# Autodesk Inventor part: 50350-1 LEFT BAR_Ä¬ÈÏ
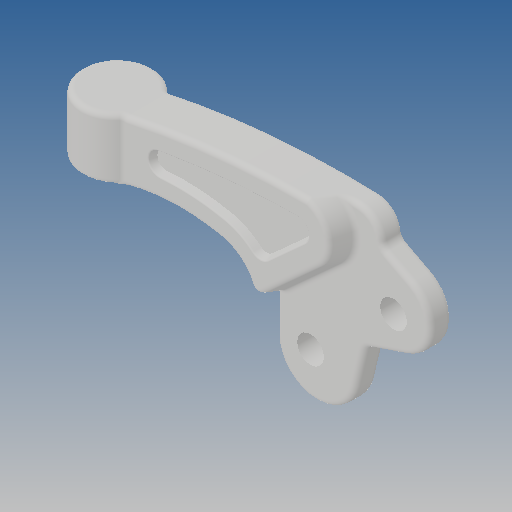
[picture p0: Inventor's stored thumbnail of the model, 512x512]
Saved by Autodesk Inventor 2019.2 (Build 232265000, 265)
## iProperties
Created: 2010-06
Part Number: 50350-1 LEFT BAR_Ä¬ÈÏ
Material: Ogólny
Document SubType Name: Modeling
Designer: CADENGINEERING4
Density: 1 g/cm^3
Appearance: Domyślna
Author: CADENGINEERING4
Revision Number: ÈÎºÎ
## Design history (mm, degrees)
feature "NONE"
node "Bryła1"
